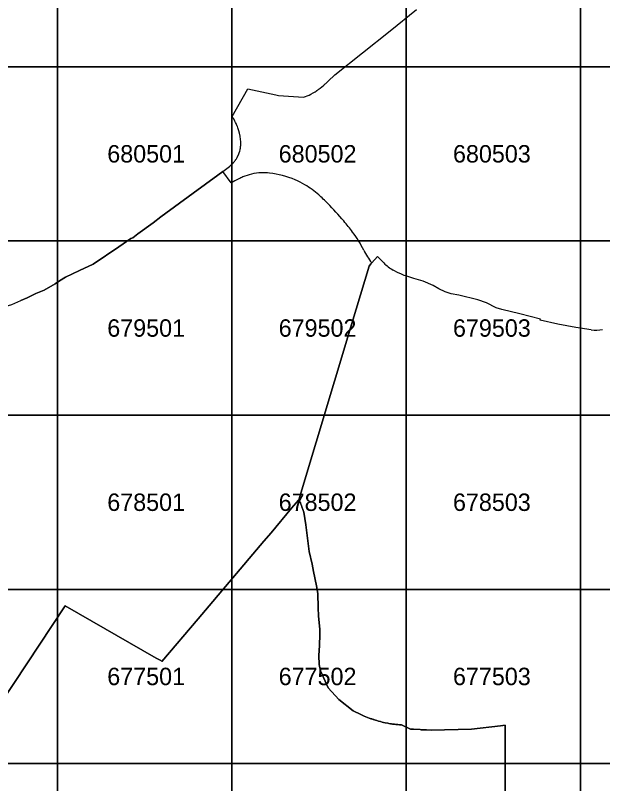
# Model space of a CAD drawing. Extents: x 25485000 to 25520000, y 6656775 to 6690000.
# Drawn here: x 25500758 to 25504127, y 6676885 to 6681295 of the extents above; entities that cross this region are included whole.
import ezdxf

# ---------------------------------------------------------------- set-up
doc = ezdxf.new("R2010")
doc.units = 0
doc.layers.add('Level 63', color=7, linetype='Continuous')

msp = doc.modelspace()

# ---------------------------------------------------------------- linework, layer by layer
at = {"layer": 'Level 63'}
for points in [[(25500000, 6681000), (25501000, 6681000), (25501000, 6682000), (25500000, 6682000)], [(25501000, 6681000), (25502000, 6681000), (25502000, 6682000), (25501000, 6682000)], [(25502000, 6681000), (25503000, 6681000), (25503000, 6682000), (25502000, 6682000)], [(25503000, 6681000), (25504000, 6681000), (25504000, 6682000), (25503000, 6682000)], [(25504000, 6681000), (25505000, 6681000), (25505000, 6682000), (25504000, 6682000)], [(25500000, 6680000), (25501000, 6680000), (25501000, 6681000), (25500000, 6681000)], [(25501000, 6680000), (25502000, 6680000), (25502000, 6681000), (25501000, 6681000)], [(25502000, 6680000), (25503000, 6680000), (25503000, 6681000), (25502000, 6681000)], [(25503000, 6680000), (25504000, 6680000), (25504000, 6681000), (25503000, 6681000)], [(25504000, 6680000), (25505000, 6680000), (25505000, 6681000), (25504000, 6681000)], [(25500000, 6679000), (25501000, 6679000), (25501000, 6680000), (25500000, 6680000)], [(25501000, 6679000), (25502000, 6679000), (25502000, 6680000), (25501000, 6680000)], [(25502000, 6679000), (25503000, 6679000), (25503000, 6680000), (25502000, 6680000)], [(25503000, 6679000), (25504000, 6679000), (25504000, 6680000), (25503000, 6680000)], [(25504000, 6679000), (25505000, 6679000), (25505000, 6680000), (25504000, 6680000)], [(25500000, 6678000), (25501000, 6678000), (25501000, 6679000), (25500000, 6679000)], [(25501000, 6678000), (25502000, 6678000), (25502000, 6679000), (25501000, 6679000)], [(25502000, 6678000), (25503000, 6678000), (25503000, 6679000), (25502000, 6679000)], [(25503000, 6678000), (25504000, 6678000), (25504000, 6679000), (25503000, 6679000)], [(25504000, 6678000), (25505000, 6678000), (25505000, 6679000), (25504000, 6679000)], [(25500000, 6677000), (25501000, 6677000), (25501000, 6678000), (25500000, 6678000)], [(25501000, 6677000), (25502000, 6677000), (25502000, 6678000), (25501000, 6678000)], [(25502000, 6677000), (25503000, 6677000), (25503000, 6678000), (25502000, 6678000)], [(25503000, 6677000), (25504000, 6677000), (25504000, 6678000), (25503000, 6678000)], [(25504000, 6677000), (25505000, 6677000), (25505000, 6678000), (25504000, 6678000)], [(25500000, 6676000), (25501000, 6676000), (25501000, 6677000), (25500000, 6677000)], [(25501000, 6676000), (25502000, 6676000), (25502000, 6677000), (25501000, 6677000)], [(25502000, 6676000), (25503000, 6676000), (25503000, 6677000), (25502000, 6677000)], [(25503000, 6676000), (25504000, 6676000), (25504000, 6677000), (25503000, 6677000)], [(25504000, 6676000), (25505000, 6676000), (25505000, 6677000), (25504000, 6677000)]]:
    msp.add_lwpolyline(points, close=True, dxfattribs=at)
for points in [[(25500789.7, 6679657.4), (25500825.2, 6679673.7), (25500875, 6679698.3), (25500923, 6679717.9), (25500985.7, 6679753.3), (25501011.6, 6679770.2), (25501044.7, 6679791.8), (25501125.7, 6679829.5), (25501203.4, 6679865.7), (25501351.9, 6679966.3), (25501420.7, 6680012.9), (25501431, 6680018.5), (25501460.7, 6680041.4), (25501547.9, 6680103.6), (25501593, 6680137.7), (25501778.3, 6680273.9), (25501919.7, 6680377.8), (25501948.8, 6680397.8), (25501986.5, 6680427.6), (25501987.8, 6680428.6), (25501990, 6680430.4), (25501991.2, 6680431.5), (25501992.8, 6680432.8), (25501994.6, 6680434.4), (25501997.2, 6680436.8), (25501998.7, 6680438.2), (25501999.8, 6680439.2), (25502001.1, 6680440.5), (25502002.1, 6680441.5), (25502003.3, 6680442.8), (25502004.7, 6680444.2), (25502006, 6680445.6), (25502006.8, 6680446.5), (25502007.9, 6680447.7), (25502008.9, 6680448.9), (25502010.2, 6680450.3), (25502010.8, 6680451.1), (25502011, 6680451.2), (25502011.2, 6680451.5), (25502011.7, 6680452.1), (25502013.8, 6680454.7), (25502015.3, 6680456.6), (25502017.3, 6680459.2), (25502018.4, 6680460.7), (25502019.6, 6680462.4), (25502020.3, 6680463.3), (25502021.6, 6680465.2), (25502022.4, 6680466.4), (25502023.5, 6680468), (25502024.2, 6680469.2), (25502025.8, 6680471.6), (25502027.7, 6680474.8), (25502029.2, 6680477.4), (25502030.4, 6680479.6), (25502031.6, 6680481.8), (25502032.8, 6680484), (25502033.6, 6680485.6), (25502034.3, 6680487.1), (25502035, 6680488.6), (25502035.8, 6680490.3), (25502036.1, 6680490.9), (25502036.1, 6680491), (25502036.2, 6680491.2), (25502036.5, 6680491.8), (25502037.3, 6680493.7), (25502037.7, 6680494.6), (25502038.3, 6680496), (25502038.3, 6680496.1), (25502039.1, 6680498), (25502040.2, 6680500.7), (25502041.9, 6680505.5), (25502044.7, 6680514.3), (25502046.8, 6680522.1), (25502047.6, 6680525.6), (25502047.9, 6680527), (25502048.1, 6680528.2), (25502048.6, 6680530.6), (25502048.8, 6680532), (25502049.5, 6680535.7), (25502050.3, 6680541.7), (25502050.8, 6680546.9), (25502051.2, 6680552.7), (25502051.2, 6680569.8), (25502050.2, 6680582.4), (25502047.2, 6680601.8), (25502043.4, 6680619.1), (25502040, 6680631.9), (25502036.6, 6680642.4), (25502034.2, 6680649.6), (25502031.4, 6680656.9), (25502030.2, 6680659.9), (25502029.4, 6680661.9), (25502028.9, 6680663.1), (25502027.1, 6680667.3), (25502026.8, 6680668), (25502026.8, 6680668.1), (25502026.6, 6680668.5), (25502026.3, 6680669.3), (25502025.9, 6680670), (25502024.3, 6680673.6), (25502021.3, 6680679.9), (25502017.2, 6680688), (25502016, 6680690.2), (25502015.2, 6680691.7), (25502013.1, 6680695.5), (25502010.5, 6680700), (25502008.2, 6680703.8), (25502006.3, 6680706.9), (25502005.5, 6680708.3), (25502003.4, 6680711.4), (25502002.5, 6680712.9), (25502002.1, 6680713.6), (25502091, 6680873.2), (25502251.9, 6680837.6), (25502267.2, 6680834.2), (25502410, 6680824.6), (25502444.1, 6680836.9), (25502453.6, 6680842), (25502466.6, 6680849.5), (25502476.9, 6680855.8), (25502483.8, 6680860.3), (25502486.9, 6680862.4), (25502489.3, 6680864), (25502493, 6680866.6), (25502497.6, 6680869.9), (25502501.7, 6680872.9), (25502506.2, 6680876.3), (25502516, 6680884.1), (25502523.1, 6680890), (25502526.4, 6680892.8), (25502529.6, 6680895.6), (25502531, 6680896.9), (25502531.7, 6680897.5), (25502532.7, 6680898.4), (25502534.2, 6680899.9), (25502535.7, 6680901.2), (25502539.1, 6680904.4), (25502540.5, 6680905.7), (25502540.8, 6680906), (25502542.6, 6680907.7), (25502544.5, 6680909.6), (25502546.8, 6680911.9), (25502552, 6680917.1), (25502590.2, 6680953.3), (25502907.5, 6681205.9), (25503060.1, 6681327.4)], [(25501995.4, 6680333.3), (25501948.8, 6680397.8), (25501986.5, 6680427.6), (25501987.8, 6680428.6), (25501990, 6680430.4), (25501991.2, 6680431.5), (25501992.8, 6680432.8), (25501994.6, 6680434.4), (25501997.2, 6680436.8), (25501998.7, 6680438.2), (25501999.8, 6680439.2), (25502001.1, 6680440.5), (25502002.1, 6680441.5), (25502003.3, 6680442.8), (25502004.7, 6680444.2), (25502006, 6680445.6), (25502006.8, 6680446.5), (25502007.9, 6680447.7), (25502008.9, 6680448.9), (25502010.2, 6680450.3), (25502010.8, 6680451.1), (25502011, 6680451.2), (25502011.2, 6680451.5), (25502011.7, 6680452.1), (25502013.8, 6680454.7), (25502015.3, 6680456.6), (25502017.3, 6680459.2), (25502018.4, 6680460.7), (25502019.6, 6680462.4), (25502020.3, 6680463.3), (25502021.6, 6680465.2), (25502022.4, 6680466.4), (25502023.5, 6680468), (25502024.2, 6680469.2), (25502025.8, 6680471.6), (25502027.7, 6680474.8), (25502029.2, 6680477.4), (25502030.4, 6680479.6), (25502031.6, 6680481.8), (25502032.8, 6680484), (25502033.6, 6680485.6), (25502034.3, 6680487.1), (25502035, 6680488.6), (25502035.8, 6680490.3), (25502036.1, 6680490.9), (25502036.1, 6680491), (25502036.2, 6680491.2), (25502036.5, 6680491.8), (25502037.3, 6680493.7), (25502037.7, 6680494.6), (25502038.3, 6680496), (25502038.3, 6680496.1), (25502039.1, 6680498), (25502040.2, 6680500.7), (25502041.9, 6680505.5), (25502044.7, 6680514.3), (25502046.8, 6680522.1), (25502047.6, 6680525.6), (25502047.9, 6680527), (25502048.1, 6680528.2), (25502048.6, 6680530.6), (25502048.8, 6680532), (25502049.5, 6680535.7), (25502050.3, 6680541.7), (25502050.8, 6680546.9), (25502051.2, 6680552.7), (25502051.2, 6680569.8), (25502050.2, 6680582.4), (25502047.2, 6680601.8), (25502043.4, 6680619.1), (25502040, 6680631.9), (25502036.6, 6680642.4), (25502034.2, 6680649.6), (25502031.4, 6680656.9), (25502030.2, 6680659.9), (25502029.4, 6680661.9), (25502028.9, 6680663.1), (25502027.1, 6680667.3), (25502026.8, 6680668), (25502026.8, 6680668.1), (25502026.6, 6680668.5), (25502026.3, 6680669.3), (25502025.9, 6680670), (25502024.3, 6680673.6), (25502021.3, 6680679.9), (25502017.2, 6680688), (25502016, 6680690.2), (25502015.2, 6680691.7), (25502013.1, 6680695.5), (25502010.5, 6680700), (25502008.2, 6680703.8), (25502006.3, 6680706.9), (25502005.5, 6680708.3), (25502003.4, 6680711.4), (25502002.5, 6680712.9), (25502002.1, 6680713.6), (25502091, 6680873.2), (25502251.9, 6680837.6), (25502267.2, 6680834.2), (25502410, 6680824.6), (25502444.1, 6680836.9), (25502453.6, 6680842), (25502466.6, 6680849.5), (25502476.9, 6680855.8), (25502483.8, 6680860.3), (25502486.9, 6680862.4), (25502489.3, 6680864), (25502493, 6680866.6), (25502497.6, 6680869.9), (25502501.7, 6680872.9), (25502506.2, 6680876.3), (25502516, 6680884.1), (25502523.1, 6680890), (25502526.4, 6680892.8), (25502529.6, 6680895.6), (25502531, 6680896.9), (25502531.7, 6680897.5), (25502532.7, 6680898.4), (25502534.2, 6680899.9), (25502535.7, 6680901.2), (25502539.1, 6680904.4), (25502540.5, 6680905.7), (25502540.8, 6680906), (25502542.6, 6680907.7), (25502544.5, 6680909.6), (25502546.8, 6680911.9), (25502552, 6680917.1), (25502590.2, 6680953.3), (25502907.5, 6681205.9), (25503060.1, 6681327.4)], [(25501995.4, 6680333.3), (25501948.8, 6680397.8), (25501919.7, 6680377.8), (25501778.3, 6680273.9), (25501593, 6680137.7), (25501547.9, 6680103.6), (25501460.7, 6680041.4), (25501431, 6680018.5), (25501420.7, 6680012.9), (25501351.9, 6679966.3), (25501203.4, 6679865.7), (25501125.7, 6679829.5), (25501044.7, 6679791.8), (25501011.6, 6679770.2), (25500985.7, 6679753.3), (25500923, 6679717.9), (25500875, 6679698.3), (25500825.2, 6679673.7), (25500789.7, 6679657.4)], [(25500377.3, 6676901.5), (25501042.6, 6677905.5), (25501565.5, 6677604.1), (25501592.8, 6677592.1), (25501598.7, 6677585.2), (25501806.1, 6677830.6), (25502183.1, 6678276.3), (25502224.5, 6678324.7), (25502342.9, 6678465), (25502381.7, 6678511.5), (25502384.1, 6678514.4), (25502689.1, 6679526.8), (25502787.9, 6679854.6), (25502796.9, 6679868.3), (25502802.1, 6679874)], [(25502871.5, 6679873.3), (25502856.5, 6679888.7), (25502836.1, 6679911.2), (25502802.1, 6679874), (25502796.9, 6679868.3), (25502787.9, 6679854.6), (25502689.1, 6679526.8), (25502384.1, 6678514.4), (25502381.7, 6678511.5), (25502386, 6678505.8), (25502393.3, 6678496), (25502395.7, 6678489.6), (25502398.7, 6678481.7), (25502401.9, 6678473.2), (25502413, 6678443.8), (25502423.7, 6678370), (25502444.1, 6678216.4), (25502461, 6678144.4), (25502467.9, 6678102.8), (25502484.6, 6678021), (25502493.9, 6677975.6), (25502495.3, 6677894.4), (25502497.2, 6677847), (25502504.3, 6677770.4), (25502503.7, 6677740.8), (25502502.6, 6677677.1), (25502498.3, 6677620.5), (25502501.3, 6677568.8), (25502508.4, 6677532.3), (25502552.3, 6677435.3), (25502613.9, 6677367.2), (25502695.8, 6677302.5), (25502739.1, 6677281.1), (25502759.3, 6677272.2), (25502767.9, 6677268.7), (25502778, 6677264.7), (25502787.4, 6677261.1), (25502793.4, 6677258.9), (25502797.8, 6677257.4), (25502802.3, 6677255.8), (25502809.7, 6677253.3), (25502813.9, 6677251.9), (25502818.6, 6677250.4), (25502823.3, 6677249), (25502830.8, 6677246.7), (25502841.1, 6677243.7), (25502851.9, 6677240.7), (25502862.5, 6677238.1), (25502869.6, 6677236.3), (25502878.6, 6677234.3), (25502893.9, 6677231.3), (25502900.5, 6677230), (25502909.8, 6677228.5), (25502915.4, 6677227.6), (25502921.6, 6677226.7), (25502929.1, 6677225.7), (25502932.4, 6677225.3), (25502940, 6677224.4), (25502946.7, 6677223.7), (25502952.4, 6677223.2), (25502961.1, 6677222.5), (25502967.9, 6677222), (25502968, 6677222), (25502969.5, 6677221.9), (25502971.1, 6677221.8), (25502973.3, 6677221.7), (25502973.3, 6677221.7), (25502973.6, 6677221.7), (25503025.3, 6677197.6), (25503036, 6677197), (25503042, 6677196.7), (25503080.8, 6677194.5), (25503085.4, 6677194.3), (25503095.1, 6677193.7), (25503116.3, 6677192.6), (25503143, 6677191.1), (25503374.2, 6677197.1), (25503540.9, 6677216.7), (25503567.2, 6677219.8), (25503567, 6676625)], [(25502871.5, 6679873.3), (25502856.5, 6679888.7), (25502836.1, 6679911.2), (25502802.1, 6679874)], [(25504061.7, 6679490.2), (25503973.4, 6679503.2), (25503869.6, 6679521.2), (25503769.4, 6679546), (25503770.6, 6679551.3), (25503652, 6679581.5), (25503548.5, 6679606.2), (25503517.1, 6679616), (25503461.2, 6679643.8), (25503411.4, 6679661.4), (25503301.3, 6679688.6), (25503258.1, 6679696.7), (25503224.2, 6679708.4), (25503188.1, 6679724), (25503154, 6679744.5), (25503096.8, 6679769.1), (25503043.6, 6679783.4), (25503004.5, 6679797.9), (25502988.6, 6679801.6), (25502968.4, 6679810.1), (25502953.7, 6679817.5), (25502925, 6679833)], [(25504061.7, 6679490.2), (25503973.4, 6679503.2), (25503869.6, 6679521.2), (25503769.4, 6679546), (25503770.6, 6679551.3), (25503652, 6679581.5), (25503548.5, 6679606.2), (25503517.1, 6679616), (25503461.2, 6679643.8), (25503411.4, 6679661.4), (25503301.3, 6679688.6), (25503258.1, 6679696.7), (25503224.2, 6679708.4), (25503188.1, 6679724), (25503154, 6679744.5), (25503096.8, 6679769.1), (25503043.6, 6679783.4), (25503004.5, 6679797.9), (25502988.6, 6679801.6), (25502968.4, 6679810.1), (25502953.7, 6679817.5), (25502925, 6679833)], [(25503567, 6676625), (25503567.2, 6677219.8), (25503540.9, 6677216.7), (25503374.2, 6677197.1), (25503143, 6677191.1), (25503116.3, 6677192.6), (25503095.1, 6677193.7), (25503085.4, 6677194.3), (25503080.8, 6677194.5), (25503042, 6677196.7), (25503036, 6677197), (25503025.3, 6677197.6), (25502973.6, 6677221.7), (25502973.3, 6677221.7), (25502973.3, 6677221.7), (25502971.1, 6677221.8), (25502969.5, 6677221.9), (25502968, 6677222), (25502967.9, 6677222), (25502961.1, 6677222.5), (25502952.4, 6677223.2), (25502946.7, 6677223.7), (25502940, 6677224.4), (25502932.4, 6677225.3), (25502929.1, 6677225.7), (25502921.6, 6677226.7), (25502915.4, 6677227.6), (25502909.8, 6677228.5), (25502900.5, 6677230), (25502893.9, 6677231.3), (25502878.6, 6677234.3), (25502869.6, 6677236.3), (25502862.5, 6677238.1), (25502851.9, 6677240.7), (25502841.1, 6677243.7), (25502830.8, 6677246.7), (25502823.3, 6677249), (25502818.6, 6677250.4), (25502813.9, 6677251.9), (25502809.7, 6677253.3), (25502802.3, 6677255.8), (25502797.8, 6677257.4), (25502793.4, 6677258.9), (25502787.4, 6677261.1), (25502778, 6677264.7), (25502767.9, 6677268.7), (25502759.3, 6677272.2), (25502739.1, 6677281.1), (25502695.8, 6677302.5), (25502613.9, 6677367.2), (25502552.3, 6677435.3), (25502508.4, 6677532.3), (25502501.3, 6677568.8), (25502498.3, 6677620.5), (25502502.6, 6677677.1), (25502503.7, 6677740.8), (25502504.3, 6677770.4), (25502497.2, 6677847), (25502495.3, 6677894.4), (25502493.9, 6677975.6), (25502484.6, 6678021), (25502467.9, 6678102.8), (25502461, 6678144.4), (25502444.1, 6678216.4), (25502423.7, 6678370), (25502413, 6678443.8), (25502401.9, 6678473.2), (25502398.7, 6678481.7), (25502395.7, 6678489.6), (25502393.3, 6678496), (25502386, 6678505.8), (25502381.7, 6678511.5), (25502342.9, 6678465), (25502224.5, 6678324.7), (25502183.1, 6678276.3), (25501806.1, 6677830.6), (25501598.7, 6677585.2), (25501592.8, 6677592.1), (25501565.5, 6677604.1), (25501042.6, 6677905.5), (25500377.3, 6676901.5)]]:
    msp.add_lwpolyline(points, dxfattribs=at)
for centre, radius, start, end in [((25502431.7, 6679546.1), 900, 115.783, 118.9956), ((25502431.7, 6679546.1), 900, 115.783, 118.9956), ((25502431.7, 6679546.1), 900, 114.2195, 115.783), ((25502431.7, 6679546.1), 900, 114.2195, 115.783), ((25502180.7, 6680091.2), 300, 103.2277, 113.2055), ((25502180.7, 6680091.2), 300, 103.2277, 113.2055), ((25502180.7, 6680091.2), 300, 92.0502, 103.2279), ((25502180.7, 6680091.2), 300, 92.0502, 103.2279), ((25502180.7, 6680091.2), 300, 83.3935, 92.05), ((25502180.7, 6680091.2), 300, 83.3935, 92.05), ((25502165.3, 6679891.7), 500, 66.7056, 84.2746), ((25502165.3, 6679891.7), 500, 66.7056, 84.2746), ((25502110.9, 6679784.5), 620, 60.1624, 66.0038), ((25502110.9, 6679784.5), 620, 60.1624, 66.0038), ((25502095.4, 6679793.7), 620, 49.4823, 58.4978), ((25502095.4, 6679793.7), 620, 49.4823, 58.4978), ((25501342.7, 6679018.1), 1700, 44.7685, 47.1784), ((25501342.7, 6679018.1), 1700, 44.7685, 47.1784), ((25501342.7, 6679018.1), 1700, 40.1518, 44.7685), ((25501342.7, 6679018.1), 1700, 40.1518, 44.7685), ((25501342.7, 6679018.1), 1700, 37.4163, 40.1519), ((25501342.7, 6679018.1), 1700, 37.4163, 40.1519), ((25502214.7, 6679688.7), 600, 25.4578, 37.1516), ((25502214.7, 6679688.7), 600, 25.4578, 37.1516), ((25503235.1, 6680196.6), 540, 207.5779, 216.6869), ((25503235.1, 6680196.6), 540, 207.5779, 216.6869), ((25503032.2, 6680030.8), 225, 224.4252, 241.5563), ((25503032.2, 6680030.8), 225, 224.4252, 241.5563), ((25500441.4, 6680432.8), 850, 283.9309, 294.1922), ((25500441.4, 6680432.8), 850, 283.9309, 294.1922), ((25504090.9, 6679688), 200, 261.6019, 280.4079), ((25504090.9, 6679688), 200, 261.6021, 280.4079)]:
    msp.add_arc(centre, radius, start, end, dxfattribs=at)

# ---------------------------------------------------------------- texts
for s, p in [('680501', (25501285.1, 6680450)), ('680502', (25502268.5, 6680450)), ('680503', (25503268.5, 6680450)), ('679501', (25501285.1, 6679450)), ('679502', (25502268.5, 6679450)), ('679503', (25503268.5, 6679450)), ('678501', (25501285.1, 6678450)), ('678502', (25502268.5, 6678450)), ('678503', (25503268.5, 6678450)), ('677501', (25501285.1, 6677450)), ('677502', (25502268.5, 6677450)), ('677503', (25503268.5, 6677450))]:
    msp.add_text(s, height=100, dxfattribs=at).set_placement(p)

doc.saveas('drawing.dxf')
